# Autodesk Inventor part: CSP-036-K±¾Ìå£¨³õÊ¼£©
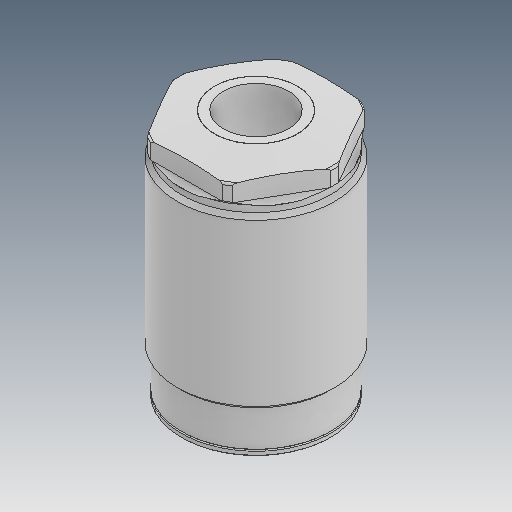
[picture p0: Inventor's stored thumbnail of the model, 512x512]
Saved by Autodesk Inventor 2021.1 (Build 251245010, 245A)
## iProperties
Created: 2019-01
Part Number: CSP-036-K±¾Ìå£¨³õÊ¼£©
Material: Ogólny
Document SubType Name: Modeling
Designer: user
Density: 1 g/cm^3
Appearance: Domyślna
Author: user
Revision Number: ÈÎºÎ
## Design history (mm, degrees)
feature "ÇÐ³ý-À­Éì2"
node "Bryła1"
